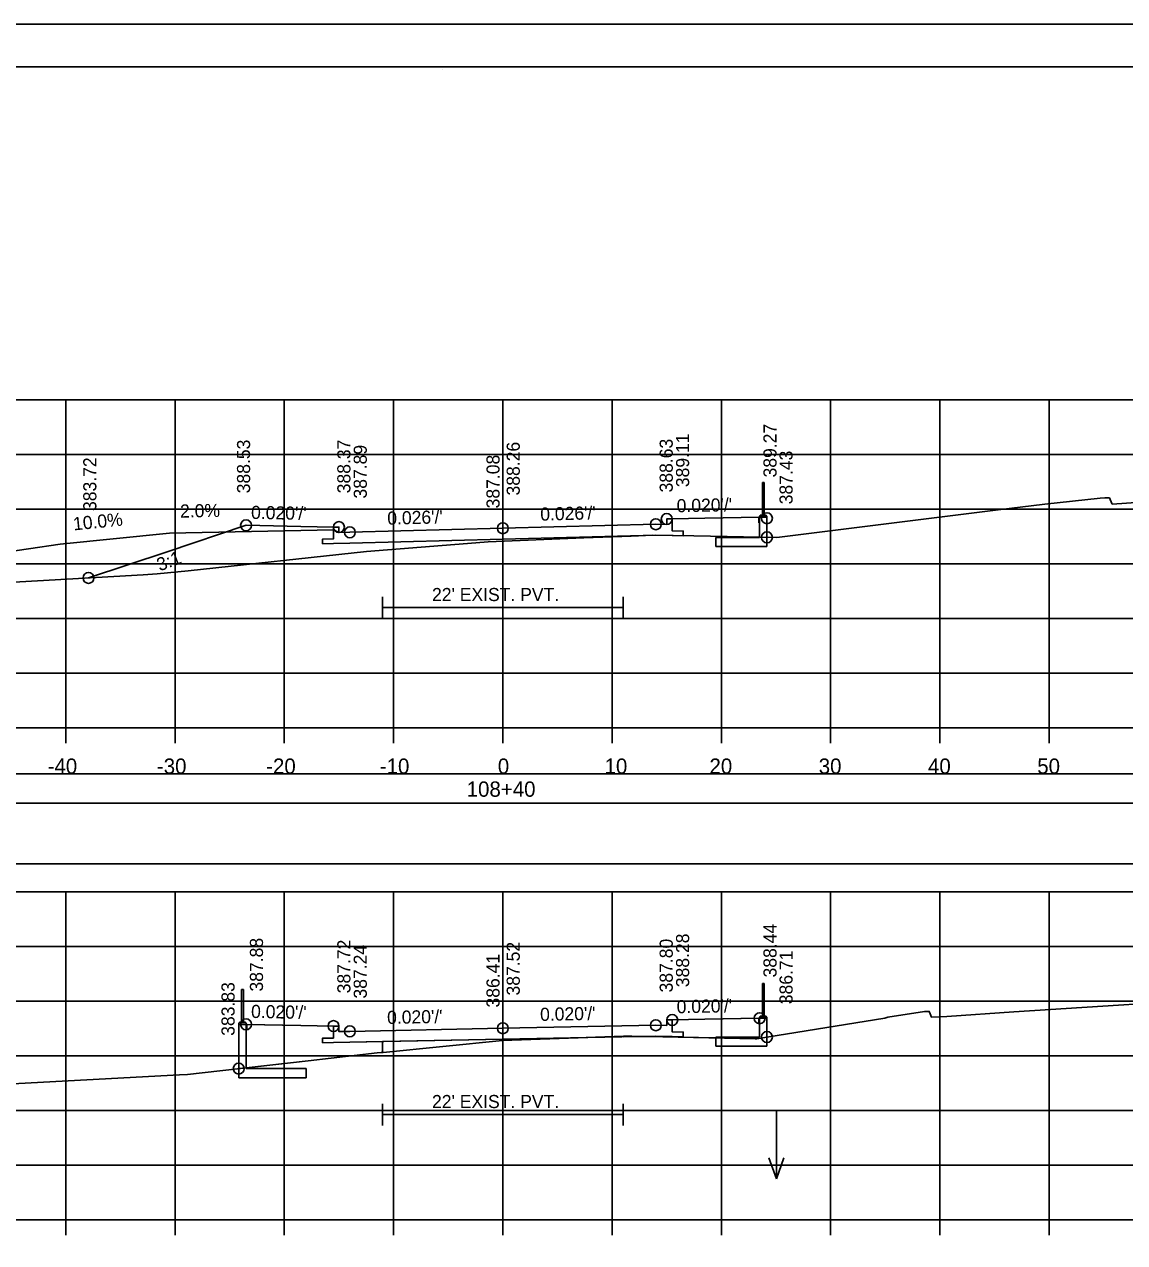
# Model space of a CAD drawing. Extents: x -37291014 to -37290680, y -936053 to -933067.
# Drawn here: x -37290886.9 to -37290786.2, y -934458 to -934346.6 of the extents above; entities that cross this region are included whole.
import ezdxf

# ---------------------------------------------------------------- set-up
doc = ezdxf.new("R2010")
doc.units = 0
for name, color, linetype in [('Default', 7, 'Continuous'), ('R_Alt Surface', 7, 'Continuous'), ('R_Axis', 7, 'Continuous'), ('R_Axis Annot', 7, 'Continuous'), ('R_Border', 7, 'Continuous'), ('R_Contours', 7, 'Continuous'), ('R_Drive', 7, 'Continuous'), ('R_Exist Surface', 7, 'Continuous'), ('R_Fin Surface', 7, 'Continuous'), ('R_Grid', 7, 'Continuous'), ('R_No Plot', 7, 'Continuous'), ('R_Water', 7, 'Continuous'), ('R_Water Annot', 7, 'Continuous'), ('R_Xsect Elev', 7, 'Continuous'), ('R_Xsect Slope', 7, 'Continuous')]:
    doc.layers.add(name, color=color, linetype=linetype)

msp = doc.modelspace()

# ---------------------------------------------------------------- linework, layer by layer
at = {"layer": 'Default'}
for p, q in [((-37290819.35, -934388.5), (-37290819.35, -934391.5)), ((-37290819.18, -934388.5), (-37290819.35, -934388.5)), ((-37290819.18, -934391.5), (-37290819.18, -934388.5)), ((-37290819.6, -934391.59), (-37290819.54, -934391.52)), ((-37290819.6, -934393.53), (-37290819.6, -934391.59)), ((-37290819.54, -934391.5), (-37290818.99, -934391.5)), ((-37290819.54, -934391.52), (-37290819.54, -934391.5)), ((-37290819.54, -934391.52), (-37290818.99, -934391.52)), ((-37290818.99, -934391.5), (-37290818.99, -934391.52)), ((-37290818.99, -934391.52), (-37290818.93, -934391.59)), ((-37290818.93, -934391.59), (-37290818.93, -934394.36)), ((-37290823.6, -934393.53), (-37290819.6, -934393.53)), ((-37290823.6, -934394.36), (-37290823.6, -934393.53)), ((-37290823.6, -934394.36), (-37290818.93, -934394.36)), ((-37290867.02, -934437.89), (-37290867.02, -934434.89)), ((-37290867.02, -934434.89), (-37290866.85, -934434.89)), ((-37290866.85, -934434.89), (-37290866.85, -934437.89)), ((-37290819.35, -934434.33), (-37290819.35, -934437.33)), ((-37290819.18, -934434.33), (-37290819.35, -934434.33)), ((-37290819.18, -934437.33), (-37290819.18, -934434.33)), ((-37290819.6, -934437.42), (-37290819.54, -934437.35)), ((-37290819.6, -934439.24), (-37290819.6, -934437.42)), ((-37290819.54, -934437.33), (-37290819, -934437.33)), ((-37290819.54, -934437.35), (-37290819.54, -934437.33)), ((-37290819.54, -934437.35), (-37290819, -934437.35)), ((-37290819, -934437.33), (-37290819, -934437.35)), ((-37290819, -934437.35), (-37290818.93, -934437.42)), ((-37290818.93, -934437.42), (-37290818.93, -934440.08)), ((-37290867.21, -934437.91), (-37290867.27, -934437.98)), ((-37290867.27, -934437.98), (-37290867.27, -934442.96)), ((-37290866.66, -934437.89), (-37290867.21, -934437.89)), ((-37290867.21, -934437.89), (-37290867.21, -934437.91)), ((-37290866.66, -934437.91), (-37290867.21, -934437.91)), ((-37290866.66, -934437.91), (-37290866.66, -934437.89)), ((-37290866.6, -934437.98), (-37290866.66, -934437.91)), ((-37290866.6, -934442.13), (-37290866.6, -934437.98)), ((-37290823.6, -934440.08), (-37290823.6, -934439.24)), ((-37290823.6, -934439.24), (-37290819.6, -934439.24)), ((-37290823.6, -934440.08), (-37290818.93, -934440.08)), ((-37290861.1, -934442.96), (-37290867.27, -934442.96)), ((-37290861.1, -934442.13), (-37290866.6, -934442.13)), ((-37290861.1, -934442.96), (-37290861.1, -934442.13))]:
    msp.add_line(p, q, dxfattribs=at)
for points in [[(-37290819.68, -934392.19), (-37290819.6, -934392.19), (-37290819.6, -934391.69), (-37290819.68, -934391.69), (-37290819.68, -934392.19)], [(-37290866.52, -934438.58), (-37290866.6, -934438.58), (-37290866.6, -934438.08), (-37290866.52, -934438.08), (-37290866.52, -934438.58)], [(-37290819.68, -934438.02), (-37290819.6, -934438.02), (-37290819.6, -934437.52), (-37290819.68, -934437.52), (-37290819.68, -934438.02)]]:
    msp.add_lwpolyline(points, dxfattribs=at)
for points in [[(-37290992.31, -934417.86), (-37290693.89, -934417.86), (-37290693.89, -934415.16), (-37290992.31, -934415.16)], [(-37290992.26, -934423.39), (-37290693.84, -934423.39), (-37290693.84, -934417.86), (-37290992.26, -934417.86)]]:
    msp.add_lwpolyline(points, close=True, dxfattribs=at)
at = {"layer": 'R_Alt Surface'}
for points in [[(-37290827.6, -934391.85), (-37290827.6, -934392.94), (-37290826.59, -934392.96), (-37290826.6, -934393.38), (-37290827.6, -934393.36), (-37290829.1, -934393.33), (-37290843.1, -934393.7), (-37290857.1, -934394.07), (-37290858.6, -934394.1), (-37290859.6, -934394.12), (-37290859.61, -934393.7), (-37290858.6, -934393.68), (-37290858.6, -934392.59)], [(-37290854.1, -934398.96), (-37290854.1, -934400.96)], [(-37290832.1, -934398.96), (-37290832.1, -934400.96)], [(-37290854.1, -934399.96), (-37290832.1, -934399.96)], [(-37290827.6, -934437.68), (-37290827.6, -934438.77), (-37290826.59, -934438.79), (-37290826.6, -934439.21), (-37290827.6, -934439.19), (-37290829.1, -934439.16), (-37290843.1, -934439.44), (-37290857.1, -934439.72), (-37290858.6, -934439.75), (-37290859.6, -934439.77), (-37290859.61, -934439.35), (-37290858.6, -934439.33), (-37290858.6, -934438.24)], [(-37290827.6, -934437.68), (-37290827.6, -934438.77), (-37290826.59, -934438.79), (-37290826.6, -934439.21), (-37290827.6, -934439.19), (-37290829.1, -934439.16), (-37290843.1, -934439.44), (-37290857.1, -934439.72), (-37290858.6, -934439.75), (-37290859.6, -934439.77), (-37290859.61, -934439.35), (-37290858.6, -934439.33), (-37290858.6, -934438.24)], [(-37290854.1, -934445.34), (-37290854.1, -934447.34)], [(-37290832.1, -934445.34), (-37290832.1, -934447.34)], [(-37290854.1, -934446.34), (-37290832.1, -934446.34)]]:
    msp.add_lwpolyline(points, dxfattribs=at)
at = {"layer": 'R_Axis'}
for p, q in [((-37290993.1, -934410.96), (-37290693.1, -934410.96)), ((-37290883.1, -934412.36), (-37290883.1, -934410.96)), ((-37290873.1, -934412.36), (-37290873.1, -934410.96)), ((-37290863.1, -934412.36), (-37290863.1, -934410.96)), ((-37290853.1, -934412.36), (-37290853.1, -934410.96)), ((-37290843.1, -934412.36), (-37290843.1, -934410.96)), ((-37290833.1, -934412.36), (-37290833.1, -934410.96)), ((-37290823.1, -934412.36), (-37290823.1, -934410.96)), ((-37290813.1, -934412.36), (-37290813.1, -934410.96)), ((-37290803.1, -934412.36), (-37290803.1, -934410.96)), ((-37290793.1, -934412.36), (-37290793.1, -934410.96)), ((-37290993.1, -934455.96), (-37290693.1, -934455.96)), ((-37290883.1, -934457.36), (-37290883.1, -934455.96)), ((-37290873.1, -934457.36), (-37290873.1, -934455.96)), ((-37290863.1, -934457.36), (-37290863.1, -934455.96)), ((-37290853.1, -934457.36), (-37290853.1, -934455.96)), ((-37290843.1, -934457.36), (-37290843.1, -934455.96)), ((-37290833.1, -934457.36), (-37290833.1, -934455.96)), ((-37290823.1, -934457.36), (-37290823.1, -934455.96)), ((-37290813.1, -934457.36), (-37290813.1, -934455.96)), ((-37290803.1, -934457.36), (-37290803.1, -934455.96)), ((-37290793.1, -934457.36), (-37290793.1, -934455.96))]:
    msp.add_line(p, q, dxfattribs=at)
at = {"layer": 'R_Border'}
for p, q in [((-37291001.1, -934350.5), (-37290684.92, -934350.5)), ((-37290848.58, -934350.76), (-37290848.58, -934350.76)), ((-37290848.58, -934350.76), (-37290848.58, -934350.76))]:
    msp.add_line(p, q, dxfattribs=at)
at = {"layer": 'R_Contours'}
for p, q in [((-37290819.6, -934439.24), (-37290819.6, -934438.02)), ((-37290866.6, -934438.58), (-37290866.6, -934442.05)), ((-37290843.1, -934439.44), (-37290854.1, -934439.66)), ((-37290835.35, -934439.28), (-37290843.1, -934439.44)), ((-37290832.1, -934439.18), (-37290832.1, -934439.22)), ((-37290832.1, -934439.22), (-37290829.96, -934439.18)), ((-37290829.96, -934439.18), (-37290823.6, -934439.31)), ((-37290823.6, -934439.24), (-37290819.6, -934439.24)), ((-37290823.6, -934439.31), (-37290823.6, -934439.24)), ((-37290823.6, -934439.31), (-37290823.6, -934440.08)), ((-37290818.93, -934440.08), (-37290818.93, -934439.24)), ((-37290854.1, -934439.66), (-37290854.1, -934440.65)), ((-37290854.1, -934440.65), (-37290854.1, -934439.66)), ((-37290823.6, -934440.08), (-37290818.93, -934440.08)), ((-37290866.6, -934442.05), (-37290867.27, -934442.13)), ((-37290867.27, -934442.96), (-37290861.1, -934442.96)), ((-37290866.6, -934442.13), (-37290866.6, -934442.05)), ((-37290861.1, -934442.13), (-37290866.6, -934442.13)), ((-37290861.1, -934442.96), (-37290861.1, -934442.13))]:
    msp.add_line(p, q, dxfattribs=at)
for points in [[(-37290866.52, -934438.08), (-37290866.52, -934438.58), (-37290866.6, -934438.58)], [(-37290858.6, -934438.24), (-37290861.6, -934438.18), (-37290866.52, -934438.08)], [(-37290854.1, -934439.66), (-37290857.1, -934439.72), (-37290858.6, -934439.75), (-37290859.6, -934439.77), (-37290859.61, -934439.35), (-37290858.6, -934439.33), (-37290858.6, -934438.24)], [(-37290827.6, -934437.68), (-37290827.6, -934438.77), (-37290826.59, -934438.79), (-37290826.6, -934439.21), (-37290827.6, -934439.19), (-37290829.1, -934439.16), (-37290829.96, -934439.18)], [(-37290819.68, -934437.52), (-37290824.6, -934437.62), (-37290827.6, -934437.68)], [(-37290819.6, -934438.02), (-37290819.68, -934438.02), (-37290819.68, -934437.52)], [(-37290854.1, -934440.65), (-37290854.04, -934440.64), (-37290843.12, -934439.55), (-37290835.35, -934439.28)], [(-37290829.96, -934439.18), (-37290831.31, -934439.15), (-37290832.05, -934439.17), (-37290832.1, -934439.18)], [(-37290818.93, -934439.24), (-37290819.87, -934439.39), (-37290820, -934439.39), (-37290823.6, -934439.31)], [(-37290866.6, -934442.05), (-37290860.93, -934441.41), (-37290854.6, -934440.7), (-37290854.25, -934440.66), (-37290854.1, -934440.65)], [(-37290867.27, -934442.13), (-37290867.27, -934442.13), (-37290867.27, -934442.96)]]:
    msp.add_lwpolyline(points, dxfattribs=at)
at = {"layer": 'R_Drive'}
for p, q in [((-37290873.6, -934393.14), (-37290883.6, -934394.14)), ((-37290858.6, -934392.84), (-37290873.6, -934393.14)), ((-37290858.1, -934393.09), (-37290858.6, -934392.84)), ((-37290883.6, -934394.14), (-37290907.68, -934397.75))]:
    msp.add_line(p, q, dxfattribs=at)
at = {"layer": 'R_Exist Surface'}
for points in [[(-37290890.03, -934397.76), (-37290876.03, -934396.95), (-37290874.73, -934396.87), (-37290871.91, -934396.58), (-37290855.58, -934394.83), (-37290845.57, -934394.03), (-37290844.43, -934393.93), (-37290835.68, -934393.58), (-37290831.37, -934393.41), (-37290829.38, -934393.33), (-37290825.61, -934393.38), (-37290818.02, -934393.55), (-37290797.77, -934391), (-37290793.5, -934390.48), (-37290788.43, -934389.96), (-37290788.02, -934389.92), (-37290787.98, -934389.92), (-37290787.58, -934389.92), (-37290787.36, -934390.42), (-37290787.33, -934390.48), (-37290775.1, -934389.63)], [(-37290898.17, -934444.06), (-37290872.69, -934442.7), (-37290871.97, -934442.66), (-37290860.93, -934441.41), (-37290854.6, -934440.7), (-37290854.25, -934440.66), (-37290854.04, -934440.64), (-37290843.12, -934439.55), (-37290832.05, -934439.17), (-37290831.31, -934439.15), (-37290820, -934439.39), (-37290819.87, -934439.39), (-37290818.94, -934439.25), (-37290808.13, -934437.5), (-37290807.88, -934437.43), (-37290804.5, -934436.89), (-37290804.43, -934436.89), (-37290804.07, -934436.9), (-37290804.04, -934436.98), (-37290803.87, -934437.41), (-37290802.46, -934437.36), (-37290796.33, -934436.94), (-37290775.25, -934435.6)], [(-37290898.17, -934444.06), (-37290872.69, -934442.7), (-37290871.97, -934442.66), (-37290860.93, -934441.41), (-37290854.6, -934440.7), (-37290854.25, -934440.66), (-37290854.04, -934440.64), (-37290843.12, -934439.55), (-37290832.05, -934439.17), (-37290831.31, -934439.15), (-37290820, -934439.39), (-37290819.87, -934439.39), (-37290818.94, -934439.25), (-37290808.13, -934437.5), (-37290807.88, -934437.43), (-37290804.5, -934436.89), (-37290804.43, -934436.89), (-37290804.07, -934436.9), (-37290804.04, -934436.98), (-37290803.87, -934437.41), (-37290802.46, -934437.36), (-37290796.33, -934436.94), (-37290775.25, -934435.6)]]:
    msp.add_lwpolyline(points, dxfattribs=at)
at = {"layer": 'R_Fin Surface'}
for points in [[(-37290881.02, -934397.24), (-37290873.81, -934394.84), (-37290866.6, -934392.43), (-37290861.6, -934392.53), (-37290858.6, -934392.59), (-37290858.1, -934392.59), (-37290858.1, -934393.09), (-37290857.1, -934393.07), (-37290843.1, -934392.7), (-37290829.1, -934392.33), (-37290828.1, -934392.35), (-37290828.1, -934391.85), (-37290827.6, -934391.85), (-37290824.6, -934391.79), (-37290819.6, -934391.69), (-37290818.93, -934391.69), (-37290818.93, -934393.53)], [(-37290867.27, -934442.13), (-37290867.27, -934438.08), (-37290866.6, -934438.08), (-37290861.6, -934438.18), (-37290858.6, -934438.24), (-37290858.1, -934438.24), (-37290858.1, -934438.74), (-37290857.1, -934438.72), (-37290843.1, -934438.44), (-37290829.1, -934438.16), (-37290828.1, -934438.18), (-37290828.1, -934437.68), (-37290827.6, -934437.68), (-37290824.6, -934437.62), (-37290819.6, -934437.52), (-37290818.93, -934437.52), (-37290818.93, -934439.24)], [(-37290867.27, -934442.13), (-37290867.27, -934438.08), (-37290866.6, -934438.08), (-37290861.6, -934438.18), (-37290858.6, -934438.24), (-37290858.1, -934438.24), (-37290858.1, -934438.74), (-37290857.1, -934438.72), (-37290843.1, -934438.44), (-37290829.1, -934438.16), (-37290828.1, -934438.18), (-37290828.1, -934437.68), (-37290827.6, -934437.68), (-37290824.6, -934437.62), (-37290819.6, -934437.52), (-37290818.93, -934437.52), (-37290818.93, -934439.24)]]:
    msp.add_lwpolyline(points, dxfattribs=at)
at = {"layer": 'R_Grid'}
for p, q in [((-37290993.1, -934380.96), (-37290693.1, -934380.96)), ((-37290883.1, -934410.96), (-37290883.1, -934380.96)), ((-37290873.1, -934410.96), (-37290873.1, -934380.96)), ((-37290863.1, -934410.96), (-37290863.1, -934380.96)), ((-37290853.1, -934410.96), (-37290853.1, -934380.96)), ((-37290843.1, -934410.96), (-37290843.1, -934380.96)), ((-37290833.1, -934410.96), (-37290833.1, -934380.96)), ((-37290823.1, -934410.96), (-37290823.1, -934380.96)), ((-37290813.1, -934410.96), (-37290813.1, -934380.96)), ((-37290803.1, -934410.96), (-37290803.1, -934380.96)), ((-37290793.1, -934410.96), (-37290793.1, -934380.96)), ((-37290993.1, -934385.96), (-37290693.1, -934385.96)), ((-37290993.1, -934390.96), (-37290693.1, -934390.96)), ((-37290993.1, -934395.96), (-37290693.1, -934395.96)), ((-37290993.1, -934400.96), (-37290693.1, -934400.96)), ((-37290993.1, -934405.96), (-37290693.1, -934405.96)), ((-37290993.1, -934410.96), (-37290693.1, -934410.96)), ((-37290993.1, -934425.96), (-37290693.1, -934425.96)), ((-37290883.1, -934455.96), (-37290883.1, -934425.96)), ((-37290873.1, -934455.96), (-37290873.1, -934425.96)), ((-37290863.1, -934455.96), (-37290863.1, -934425.96)), ((-37290853.1, -934455.96), (-37290853.1, -934425.96)), ((-37290843.1, -934455.96), (-37290843.1, -934425.96)), ((-37290833.1, -934455.96), (-37290833.1, -934425.96)), ((-37290823.1, -934455.96), (-37290823.1, -934425.96)), ((-37290813.1, -934455.96), (-37290813.1, -934425.96)), ((-37290803.1, -934455.96), (-37290803.1, -934425.96)), ((-37290793.1, -934455.96), (-37290793.1, -934425.96)), ((-37290993.1, -934430.96), (-37290693.1, -934430.96)), ((-37290993.1, -934435.96), (-37290693.1, -934435.96)), ((-37290993.1, -934440.96), (-37290693.1, -934440.96)), ((-37290993.1, -934445.96), (-37290693.1, -934445.96)), ((-37290993.1, -934450.96), (-37290693.1, -934450.96)), ((-37290993.1, -934455.96), (-37290693.1, -934455.96))]:
    msp.add_line(p, q, dxfattribs=at)
at = {"layer": 'R_No Plot'}
msp.add_line((-37291013.5, -934346.6), (-37290680.17, -934346.6), dxfattribs=at)
for points in [[(-37291013.51, -934346.6), (-37290680.17, -934346.6), (-37290680.17, -934559.94), (-37291013.51, -934559.94)], [(-37290767.18, -934350.5), (-37290747.56, -934350.5), (-37290747.56, -934360.38), (-37290731.45, -934360.38), (-37290708.25, -934360.38), (-37290708.25, -934384.71), (-37290684.92, -934384.71), (-37290684.92, -934555.96), (-37291001.1, -934555.96), (-37291001.1, -934350.5)]]:
    msp.add_lwpolyline(points, close=True, dxfattribs=at)
for centre in [(-37290828.1, -934391.85), (-37290818.93, -934391.78), (-37290866.6, -934392.43), (-37290858.1, -934392.59), (-37290857.1, -934393.07), (-37290843.1, -934392.7), (-37290829.1, -934392.33), (-37290818.93, -934393.53), (-37290881.02, -934397.24), (-37290827.6, -934437.68), (-37290819.6, -934437.52), (-37290866.6, -934438.08), (-37290858.6, -934438.24), (-37290857.1, -934438.72), (-37290843.1, -934438.44), (-37290829.1, -934438.16), (-37290829.1, -934438.16), (-37290818.93, -934439.24), (-37290867.27, -934442.13)]:
    msp.add_circle(centre, 0.5, dxfattribs=at)
at = {"layer": 'R_Water Annot'}
for p, q in [((-37290818.07, -934445.93), (-37290818.07, -934452.22)), ((-37290818.07, -934452.22), (-37290818.77, -934450.29)), ((-37290818.07, -934452.22), (-37290817.37, -934450.29))]:
    msp.add_line(p, q, dxfattribs=at)
at = {"layer": 'R_Xsect Elev'}
for p, q in [((-37290843.1, -934393.88), (-37290843.1, -934383.88)), ((-37290843.1, -934439.54), (-37290843.1, -934429.54)), ((-37290843.1, -934439.54), (-37290843.1, -934429.54))]:
    msp.add_line(p, q, dxfattribs=at)

# ---------------------------------------------------------------- texts
at = {"layer": 'R_Axis Annot'}
for s, p in [('-40', (-37290884.76, -934415.16)), ('-30', (-37290874.76, -934415.16)), ('-20', (-37290864.76, -934415.16)), ('-10', (-37290854.36, -934415.16)), ('0', (-37290843.56, -934415.16)), ('10', (-37290833.79, -934415.16)), ('20', (-37290824.19, -934415.16)), ('30', (-37290814.19, -934415.16)), ('40', (-37290804.19, -934415.16)), ('50', (-37290794.19, -934415.16)), ('108+40', (-37290846.41, -934417.26))]:
    msp.add_text(s, height=1.4, dxfattribs=at).set_placement(p)
at = {"layer": 'R_Water'}
for p in [(-37290849.58, -934399.36), (-37290849.58, -934445.74)]:
    msp.add_text("22' EXIST. PVT.", height=1.2, dxfattribs=at).set_placement(p)
at = {"layer": 'R_Xsect Elev'}
for s, rotation, p in [('389.27', 90, (-37290818.05, -934388.05)), ('388.53', 90, (-37290866.23, -934389.5)), ('388.37', 90, (-37290857.05, -934389.5)), ('388.26', 90, (-37290841.55, -934389.7)), ('388.63', 90, (-37290827.55, -934389.42)), ('389.11', 90, (-37290826.05, -934388.94)), ('387.89', 90, (-37290855.55, -934389.98)), ('387.08', 90, (-37290843.4, -934390.88)), ('387.43', 90, (-37290816.58, -934390.51)), ('383.72', 90, (-37290880.3, -934391.12)), ('2.0%', 1.1458, (-37290872.63, -934391.73)), ('10.0%', 5.7106, (-37290882.37, -934392.9)), ('388.44', 90, (-37290818.05, -934433.79)), ('387.88', 90, (-37290865.05, -934435.08)), ('387.72', 90, (-37290857.05, -934435.24)), ('387.52', 90, (-37290841.55, -934435.44)), ('387.80', 90, (-37290827.55, -934435.16)), ('388.28', 90, (-37290826.05, -934434.68)), ('387.24', 90, (-37290855.55, -934435.72)), ('386.41', 90, (-37290843.4, -934436.54)), ('386.41', 90, (-37290843.4, -934436.54)), ('386.71', 90, (-37290816.58, -934436.24)), ('383.83', 90, (-37290867.65, -934439.13))]:
    msp.add_text(s, height=1.2, rotation=rotation, dxfattribs=at).set_placement(p)
at = {"layer": 'R_Xsect Slope'}
for s, rotation, p in [("0.020'/'", 1.1458, (-37290827.18, -934391.24)), ("0.020'/'", 358.8542, (-37290866.15, -934391.84)), ("0.026'/'", 1.5141, (-37290853.66, -934392.38)), ("0.026'/'", 1.5141, (-37290839.66, -934392.01)), ('3:1', 20.7828, (-37290874.5, -934396.65)), ("0.020'/'", 358.8542, (-37290866.15, -934437.49)), ("0.020'/'", 358.8542, (-37290866.15, -934437.49)), ("0.020'/'", 1.1458, (-37290827.18, -934437.07)), ("0.020'/'", 1.1458, (-37290827.18, -934437.07)), ("0.020'/'", 1.1458, (-37290853.68, -934438.05)), ("0.020'/'", 1.1458, (-37290839.68, -934437.77)), ("0.020'/'", 1.1458, (-37290839.68, -934437.77))]:
    msp.add_text(s, height=1.2, rotation=rotation, dxfattribs=at).set_placement(p)

doc.saveas('drawing.dxf')
